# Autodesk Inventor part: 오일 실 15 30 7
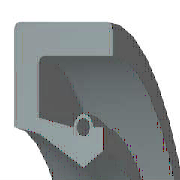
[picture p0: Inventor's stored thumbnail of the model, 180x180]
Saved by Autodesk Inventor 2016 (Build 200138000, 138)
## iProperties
IsCustomPart: 1
Created: 2012-02
Part Number: 오일 실 15 30 7
Material: 고무
Description: 오일-실
Document SubType Name: Modeling
Standard: KS B 2804
Designer: mduedu
Standards Organization: KS
Language: ko-KR
Size Designation: S - 15 30 7
Categories: <MemberInstance><Categories><Category DisplayName="샤프트 부품" InternalName="7f7aeb1f-a693-4053-b835-cee3144e0d98" Mnemonic="SHFT"><Category DisplayName="실링" Intern
Density: 0.93 g/cm^3
Appearance: 고무 - 검은색 - 버전 1.1
Author: mduedu
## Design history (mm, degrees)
revolve "본체" stored, may be unused: angle "d17" = 90 deg
revolve "스프링1" stored, may be unused: angle "d18" = 90 deg
body "Solid1"
sketch "스케치1"
  geometry: L1 (0, 15)-(7, 15); L2 (7, 15)-(7, 13.75); L3 (7, 13.75)-(1.75, 13.75); L4 (0, 15)-(0, 9.6); L5 (0, 9.6)-(1.75, 9.25); L6 (1.75, 9.25)-(4.9, 7.5); L7 (4.9, 7.5)-(0, 7.5); L8 (6.3, 8.375)-(6.3, 9.6); L9 (0, 0)-(9.586, 0) reference; L10 (4.9, 7.5)-(6.3, 8.375); L11 (0, 18)-(0, -3) reference; L12 (-1.917, 0)-(11.503, 0) reference; L13 (4.2, 9.6)-(1.75, 10.09); L14 (1.75, 10.09)-(1.75, 13.75); L15 (6.3, 9.6)-(5.6, 9.6); C1 r 0.455 at (4.9, 9.6); A1 r 0.7 centre (4.9, 9.6) between (5.6, 9.6) and (4.2, 9.6)
  constraints: 26 end point, 5 horizontal alignment, 4 perpendicular, 2 centre point, 2 collinear, 2 horizontal, 2 parallel, 2 point on circle, 2 point on line, 2 vertical alignment, 1 coincident
  dimensions: "d0" = 30 diameter of L1 L9 (= SD2); "d1" = 16.75 diameter of L8.start L9 (= ABDM); "d2" = 1.25 distance of L1.end L2.end (computed from SD); "d3" = 0.91 diameter of C1 (= SPDI); "d4" = 1.4 diameter of A1 (= SPDA); "d5" = 15 diameter of L6.end L9 (= NND); "d6" = 18.5 diameter of L5.end L9 (= TKDM); "d7" = 19.2 diameter of L4.end L9 (= HLDM); "d8" = 4.9 distance from line of C1.centre L4 (= SPDST); "d9" = 6.3 distance between parallel lines of L8 L4 (= SDI); "d10" = 7 distance between parallel lines of L2 L4 (= SWDT); "d12" = 1.75 distance between parallel lines of L14 L4 (= SD)
fillet "모깎기1" dims "d11" = 0.3 (= RR)
other parameters: "SD2" = 30 [user parameter; used in 1 equation term], "SWDT" = 7 [user parameter; used in 1 equation term], "RR" = 0.3 [user parameter; used in 1 equation term], "SD" = 1.75 [user parameter; used in 2 equation terms], "NND" = 15 [user parameter; used in 1 equation term], "SPDA" = 1.4 [user parameter; used in 1 equation term], "SPDI" = 0.91 [user parameter; used in 1 equation term], "TKDM" = 18.5 [user parameter; used in 1 equation term], "HLDM" = 19.2 [user parameter; used in 1 equation term], "ABDM" = 16.75 [user parameter; used in 1 equation term], "SDI" = 6.3 [user parameter; used in 1 equation term], "SPDST" = 4.9 [user parameter; used in 1 equation term], "d13" = 0, "d14" = 0, "d15" = 0, "LAB" = 0.35 [user parameter]
